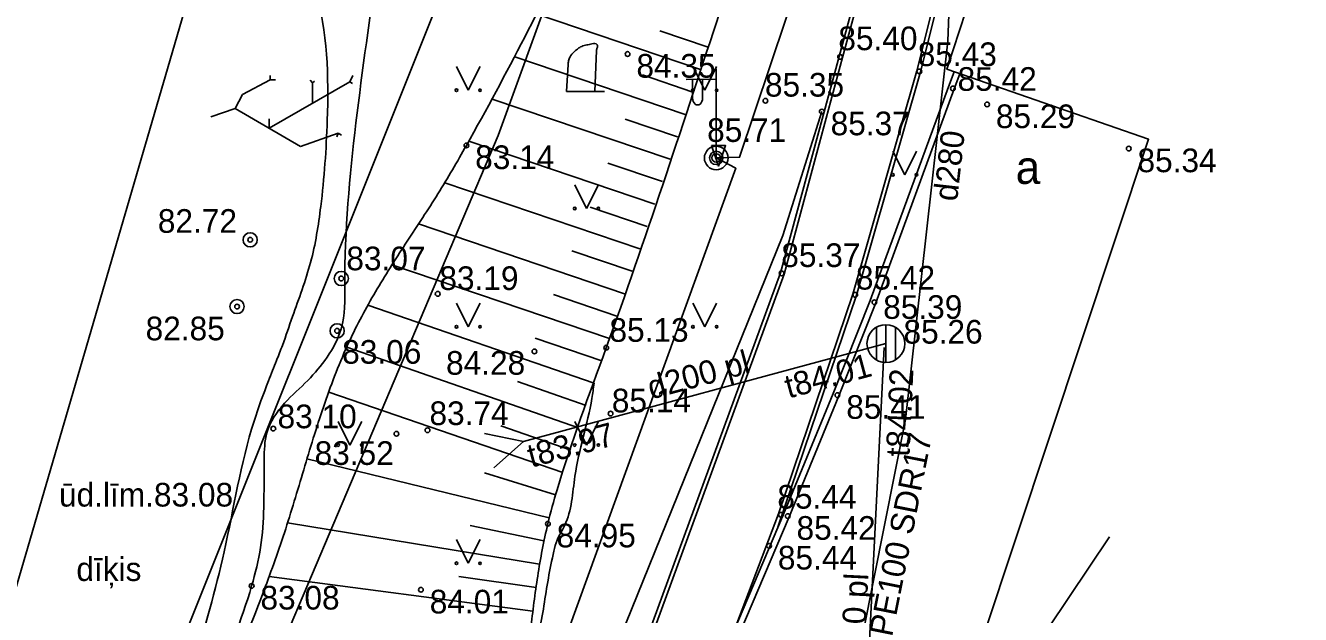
# Model space of a CAD drawing. Extents: x 576692 to 577659, y 273254 to 273799.
# Drawn here: x 576848.14 to 576875.09, y 273561.42 to 273573.87 of the extents above; entities that cross this region are included whole.
import ezdxf

# ---------------------------------------------------------------- set-up
doc = ezdxf.new("R2010")
doc.units = 0
for name, color, linetype in [('BUVE_DUMI_####_####_#', 7, 'Continuous'), ('BUVE_EKAS_####_####_#', 7, 'Continuous'), ('BUVE_EKAS_ADRS_TKST_#', 7, 'Continuous'), ('BUVE_EKAS_VNOS_TKST_#', 7, 'Continuous'), ('CELI_CMAL_####_####_#', 7, 'Continuous'), ('CELI_TAKA_####_####_#', 7, 'Continuous'), ('ELEK_STUT_####_####_#', 7, 'Continuous'), ('ELEK_VADP_ZSPR_####_#', 7, 'Continuous'), ('ELEK_VADV_ZSPR_TKST_#', 7, 'Continuous'), ('GAZE_ELEM_####_####_#', 7, 'Continuous'), ('GAZE_VADP_ZSPD_TKST_#', 7, 'Continuous'), ('GEOD_SITP_####_TKST_#', 7, 'Continuous'), ('HIDT_CAUR_####_TKST_#', 7, 'Continuous'), ('HIDT_REZV_####_TKST_#', 7, 'Continuous'), ('Level 46', 7, 'Continuous'), ('LKAN_ELEM_####_####_#', 7, 'Continuous'), ('LKAN_ELEM_PAST_TKST_#', 7, 'Continuous'), ('LKAN_VADP_PAST_####_I', 7, 'Continuous'), ('NORB_ELEM_####_####_#', 7, 'Continuous'), ('NORB_ZOGS_ZSTP_####_#', 7, 'Continuous'), ('RELJ_ELEM_####_####_#', 7, 'Continuous'), ('SAKK_KKAN_####_####_#', 7, 'Continuous'), ('SAKT_ELEM_####_####_#', 7, 'Continuous'), ('SILT_VADP_UDEN_####_#', 7, 'Continuous'), ('TERT_DIAM_####_TKST_#', 7, 'Continuous'), ('TERT_IZMT_####_TKST_#', 7, 'Continuous'), ('TERT_KONT_####_####_#', 7, 'Continuous'), ('TERT_KRND_####_####_#', 7, 'Continuous'), ('UDTK_VADP_UDEN_####_#', 7, 'Continuous')]:
    doc.layers.add(name, color=color, linetype=linetype)

msp = doc.modelspace()

# ---------------------------------------------------------------- linework, layer by layer
at = {"layer": 'BUVE_EKAS_####_####_#'}
msp.add_line((576867.65, 273572.572), (576867.769, 273572.889), dxfattribs=at)
for points in [[(576872.524, 273601.554), (576871.549, 273595.701), (576870.466, 273589.844), (576869.957, 273588.102), (576868.426, 273583.638), (576867.442, 273580.676), (576866.71, 273578.276), (576865.337, 273573.21), (576864.099, 273568.638), (576860.979, 273560.111), (576855.397, 273548.516), (576851.429, 273541.409), (576846.31, 273533.145), (576841.007, 273525.445), (576837.465, 273520.678), (576833.294, 273515.306), (576829.531, 273511.07)], [(576872.603, 273601.541), (576871.628, 273595.687), (576870.544, 273589.825), (576870.033, 273588.077), (576868.502, 273583.612), (576867.518, 273580.651), (576866.787, 273578.254), (576865.414, 273573.189), (576864.175, 273568.613), (576861.053, 273560.08), (576855.468, 273548.479), (576851.498, 273541.368), (576846.377, 273533.101), (576841.072, 273525.398), (576837.529, 273520.63), (576833.355, 273515.255), (576829.586, 273511.012)], [(576874.399, 273600.589), (576874.091, 273600.456), (576873.946, 273600.177), (576872.621, 273592.28), (576872.31, 273590.551), (576871.737, 273588.382), (576871.426, 273587.391), (576870.11, 273583.537), (576867.982, 273576.895), (576866.982, 273572.91), (576865.628, 273568.191), (576864.056, 273563.546), (576863.156, 273561.168)], [(576874.431, 273600.515), (576874.149, 273600.394), (576874.023, 273600.151), (576872.7, 273592.267), (576872.388, 273590.534), (576871.814, 273588.36), (576871.502, 273587.366), (576870.186, 273583.512), (576868.059, 273576.873), (576867.059, 273572.89), (576865.705, 273568.168), (576864.045, 273563.262)], [(576867.772, 273572.528), (576867.892, 273572.847)], [(576830.649, 273509.884), (576834.382, 273514.243), (576838.438, 273519.296), (576842.214, 273524.414), (576847.656, 273532.314), (576852.745, 273540.529), (576856.712, 273547.652), (576862.459, 273559.523), (576864.161, 273563.536), (576865.211, 273566.091), (576865.992, 273568.054), (576867.65, 273572.572)], [(576830.738, 273509.789), (576834.482, 273514.16), (576838.541, 273519.217), (576842.319, 273524.339), (576847.765, 273532.243), (576852.857, 273540.463), (576856.828, 273547.592), (576862.577, 273559.47), (576864.281, 273563.485), (576865.332, 273566.043), (576866.113, 273568.007), (576867.772, 273572.528)]]:
    msp.add_lwpolyline(points, dxfattribs=at)
at = {"layer": 'BUVE_EKAS_ADRS_TKST_#'}
for p, q in [((576853.313, 273572.721), (576853.313, 273572.812)), ((576855, 273572.675), (576855.058, 273572.811)), ((576852.732, 273572.41), (576853.313, 273572.721)), ((576853.294, 273571.698), (576855, 273572.675)), ((576853.313, 273572.721), (576853.427, 273572.721)), ((576854.206, 273572.655), (576854.161, 273572.71)), ((576854.206, 273572.655), (576854.249, 273572.691)), ((576854.206, 273572.22), (576854.206, 273572.655)), ((576855, 273572.675), (576855.055, 273572.642)), ((576852.576, 273572.117), (576852.732, 273572.41)), ((576852.058, 273571.938), (576852.576, 273572.117)), ((576852.576, 273572.117), (576853.956, 273571.311)), ((576853.294, 273571.698), (576853.294, 273571.898)), ((576853.956, 273571.311), (576854.754, 273571.589)), ((576854.754, 273571.589), (576854.723, 273571.516)), ((576854.754, 273571.589), (576854.822, 273571.549))]:
    msp.add_line(p, q, dxfattribs=at)
for centre in [(576852.891, 273569.338), (576854.817, 273568.52), (576852.613, 273567.927), (576854.729, 273567.414)]:
    msp.add_circle(centre, 0.15, dxfattribs=at)
at = {"layer": 'BUVE_EKAS_VNOS_TKST_#'}
msp.add_lwpolyline([(576863.749, 273554.185), (576865.629, 273559.935), (576866.744, 273565.541), (576867.64, 273573.538), (576867.908, 273580.684)], dxfattribs=at)
at = {"layer": 'CELI_TAKA_####_####_#'}
for points in [[(577046.926, 273445.044), (577014.811, 273425.219), (577003.88, 273430.992), (576984.145, 273436.674), (576957.338, 273444.294), (576939.479, 273446.802), (576902.067, 273445.778), (576895.402, 273442.827), (576880.902, 273442.095), (576847.668, 273445.309), (576837.012, 273452.428), (576828.656, 273463.092), (576806.624, 273484.507), (576830.977, 273509.535), (576825.208, 273515.66), (576822.783, 273520.141), (576835.572, 273532.408), (576845.616, 273554.029), (576851.92, 273575.614), (576848.447, 273595.284), (576850.413, 273611.975)], [(576875.901, 273608.92), (576873.238, 273590.115), (576867.618, 273572.942), (576871.879, 273571.462), (576866.284, 273554.628), (576861.302, 273546.668), (576863.144, 273537.44), (576882.478, 273539.149), (576882.478, 273547.068), (576949.529, 273561.695), (576947.673, 273570.204), (576952.647, 273577.562), (576971.581, 273573.757), (576961.116, 273540.729), (576960.89, 273535.214), (576957.213, 273535.221), (576957.586, 273512.35), (577020.812, 273504.477), (577024.699, 273507.761), (577034.918, 273498.457), (577056.159, 273496.649)]]:
    msp.add_lwpolyline(points, dxfattribs=at)
at = {"layer": 'ELEK_STUT_####_####_#'}
msp.add_spline([(576834.972, 273524.846), (576834.981, 273524.858), (576835.076, 273524.972), (576835.584, 273525.586), (576836.158, 273526.138), (576836.592, 273526.462), (576837.181, 273526.962), (576837.416, 273527.441), (576837.427, 273527.666), (576837.401, 273527.894), (576837.373, 273528.121), (576837.379, 273528.346), (576837.512, 273528.905), (576839.387, 273532.93), (576840.983, 273536.22), (576844.889, 273545.065), (576846.213, 273548.112), (576848.25, 273552.277), (576849.905, 273555.581), (576850.972, 273558.076), (576851.693, 273560.342), (576852.34, 273562.741), (576852.972, 273565.505), (576853.28, 273566.359), (576853.448, 273566.787), (576853.572, 273567.107), (576853.785, 273567.715), (576854.168, 273568.861), (576854.383, 273570.043), (576854.52, 273571.86), (576854.267, 273574.626), (576854.166, 273574.92), (576854.037, 273575.203), (576853.91, 273575.486), (576853.818, 273575.781), (576853.767, 273576.515), (576853.826, 273577.256), (576853.898, 273577.998), (576853.888, 273578.732), (576853.807, 273579.184), (576853.694, 273579.634), (576853.591, 273580.086), (576853.539, 273580.542), (576853.502, 273583.663), (576853.535, 273586.13), (576853.544, 273586.746), (576853.569, 273587.054), (576853.626, 273587.362), (576854.091, 273587.713), (576855.035, 273587.927), (576855.509, 273587.995), (576856.157, 273588.043), (576856.618, 273588.065), (576856.725, 273588.125), (576856.752, 273588.242), (576856.674, 273588.341), (576856.515, 273588.366), (576855.448, 273588.455), (576855.093, 273588.426), (576854.738, 273588.366), (576854.383, 273588.3), (576854.028, 273588.254), (576853.388, 273588.304), (576853.149, 273588.568), (576853.124, 273588.995), (576853.2, 273591.212), (576853.212, 273592.376), (576853.166, 273592.947), (576853.072, 273593.225), (576852.923, 273593.494), (576852.604, 273593.842), (576852.245, 273594.123), (576851.604, 273594.55), (576851.252, 273595.166), (576851.252, 273596.146), (576851.403, 273598.132), (576851.927, 273600.965), (576852.459, 273603.438)], degree=3, dxfattribs=at)
at = {"layer": 'ELEK_VADP_ZSPR_####_#'}
msp.add_lwpolyline([(576858.668, 273565.077), (576866.328, 273567.144)], dxfattribs=at)
at = {"layer": 'ELEK_VADV_ZSPR_TKST_#'}
for points in [[(576865.709, 273555.378), (576866.292, 273567.062)], [(576865.867, 273555.326), (576871.052, 273563.06)]]:
    msp.add_lwpolyline(points, dxfattribs=at)
at = {"layer": 'GAZE_ELEM_####_####_#'}
for p, q in [((576862.407, 273572.935), (576858.934, 273574.114)), ((576862.568, 273573.409), (576861.548, 273573.755)), ((576862.086, 273571.988), (576858.463, 273573.216)), ((576862.247, 273572.462), (576861.182, 273572.822)), ((576861.765, 273571.041), (576857.988, 273572.319)), ((576861.926, 273571.515), (576860.816, 273571.891)), ((576861.445, 273570.094), (576857.511, 273571.425)), ((576861.605, 273570.567), (576860.449, 273570.959)), ((576861.124, 273569.147), (576857.002, 273570.542)), ((576861.285, 273569.62), (576860.079, 273570.028)), ((576860.804, 273568.199), (576856.448, 273569.674)), ((576860.964, 273568.673), (576859.693, 273569.103)), ((576860.483, 273567.252), (576855.888, 273568.808)), ((576860.159, 273566.306), (576855.379, 273567.958)), ((576860.643, 273567.726), (576859.3, 273568.181)), ((576860.322, 273566.779), (576858.914, 273567.261)), ((576859.83, 273565.362), (576854.931, 273567.07)), ((576859.995, 273565.834), (576858.541, 273566.341)), ((576859.502, 273564.417), (576854.55, 273566.116)), ((576859.666, 273564.89), (576858.187, 273565.405)), ((576859.213, 273563.461), (576854.091, 273564.707)), ((576859.342, 273563.944), (576857.842, 273564.413)), ((576859.009, 273562.482), (576853.682, 273563.358)), ((576859.101, 273562.973), (576857.541, 273563.302)), ((576858.866, 273561.492), (576853.295, 273562.222)), ((576858.933, 273561.988), (576857.3, 273562.22))]:
    msp.add_line(p, q, dxfattribs=at)
msp.add_spline([(576837.927, 273521.787), (576838.645, 273522.875), (576839.138, 273523.968), (576839.325, 273524.31), (576840.566, 273526.148), (576844.476, 273531.952), (576846.478, 273535.631), (576849.875, 273542.091), (576852.37, 273547.073), (576852.835, 273547.871), (576853.349, 273548.641), (576853.868, 273549.409), (576854.351, 273550.199), (576857.795, 273557.24), (576858.42, 273558.892), (576858.657, 273559.995), (576858.817, 273561.113), (576858.969, 273562.231), (576859.183, 273563.337), (576859.378, 273564.056), (576860.417, 273567.058), (576862.753, 273573.954), (576864.533, 273579.174), (576866.114, 273583.695), (576866.428, 273584.761), (576866.683, 273585.844), (576866.928, 273586.93), (576867.213, 273588.005), (576867.419, 273588.612), (576867.767, 273589.444), (576868.162, 273590.255), (576868.541, 273591.08), (576868.705, 273591.507), (576868.841, 273591.951), (576868.878, 273592.605), (576868.852, 273593.138), (576868.802, 273593.672), (576868.76, 273594.206), (576868.758, 273594.74), (576868.878, 273595.276), (576870.132, 273598.247), (576870.705, 273599.436), (576871.14, 273600.337), (576871.192, 273600.445), (576871.479, 273601.144)], degree=3, dxfattribs=at)
at = {"layer": 'GEOD_SITP_####_TKST_#'}
msp.add_spline([(576860.159, 273566.306), (576860.113, 273565.987), (576859.755, 273564.34), (576859.537, 273563.302), (576859.377, 273562.992), (576859.31, 273562.756), (576859.193, 273562.183), (576859.099, 273561.604), (576858.839, 273560.463), (576858.659, 273560.007)], degree=3, dxfattribs=at)
at = {"layer": 'Level 46'}
msp.add_lwpolyline([(576819.084, 273508.06), (576836.748, 273524.115), (576867.586, 273601.172), (576868.039, 273663.467), (576868.105, 273672.497), (576868.105, 273672.497)], dxfattribs=at)
at = {"layer": 'LKAN_ELEM_####_####_#'}
msp.add_lwpolyline([(576849.004, 273551.431), (576853.733, 273561.172), (576858.13, 273571.54), (576862.062, 273582.382), (576864.74, 273591.4), (576865.79, 273595.589), (576867.357, 273605.525), (576868.834, 273616.371), (576869.677, 273625.341)], dxfattribs=at)
at = {"layer": 'LKAN_ELEM_PAST_TKST_#'}
for p, q in [((576860.179, 273572.473), (576860.213, 273573.338)), ((576857.25, 273573), (576857.5, 273572.5)), ((576857.5, 273572.5), (576857.75, 273573)), ((576859.61, 273573.046), (576859.579, 273572.473)), ((576862.25, 273573), (576862.5, 273572.5)), ((576862.5, 273572.5), (576862.75, 273573)), ((576860.179, 273572.473), (576859.579, 273572.473)), ((576859.579, 273572.473), (576859.879, 273572.473)), ((576859.879, 273572.473), (576860.179, 273572.473)), ((576860.179, 273572.473), (576860.379, 273572.473)), ((576866.475, 273571.213), (576866.725, 273570.713)), ((576866.725, 273570.713), (576866.975, 273571.213)), ((576859.75, 273570.5), (576860, 273570)), ((576860, 273570), (576860.25, 273570.5)), ((576857.25, 273568), (576857.5, 273567.5)), ((576857.5, 273567.5), (576857.75, 273568)), ((576862.25, 273568), (576862.5, 273567.5)), ((576862.5, 273567.5), (576862.75, 273568)), ((576854.75, 273565.5), (576855, 273565)), ((576855, 273565), (576855.25, 273565.5)), ((576859.75, 273565.5), (576860, 273565)), ((576860, 273565), (576860.25, 273565.5)), ((576857.25, 273563), (576857.5, 273562.5)), ((576857.5, 273562.5), (576857.75, 273563))]:
    msp.add_line(p, q, dxfattribs=at)
for centre, radius in [((576857.25, 273572.5), 0.028), ((576857.75, 273572.5), 0.0263), ((576862.25, 273572.5), 0.028), ((576862.75, 273572.5), 0.0263), ((576866.475, 273570.713), 0.028), ((576866.975, 273570.713), 0.0263), ((576859.75, 273570), 0.028), ((576860.25, 273570), 0.0263), ((576857.25, 273567.5), 0.028), ((576857.75, 273567.5), 0.0263), ((576862.25, 273567.5), 0.028), ((576862.75, 273567.5), 0.0263), ((576854.75, 273565), 0.028), ((576855.25, 273565), 0.0263), ((576859.75, 273565), 0.028), ((576860.25, 273565), 0.0263), ((576857.25, 273562.5), 0.028), ((576857.75, 273562.5), 0.0263)]:
    msp.add_circle(centre, radius, dxfattribs=at)
msp.add_spline([(576860.213, 273573.338), (576860.217, 273573.369), (576860.22, 273573.38), (576860.235, 273573.442), (576860.205, 273573.477), (576860.083, 273573.471), (576859.979, 273573.453), (576859.873, 273573.414), (576859.808, 273573.37), (576859.733, 273573.306), (576859.653, 273573.208), (576859.622, 273573.119), (576859.61, 273573.045)], degree=3, dxfattribs=at)
at = {"layer": 'LKAN_VADP_PAST_####_I'}
msp.add_spline([(576835.08, 273524.732), (576835.565, 273525.331), (576835.899, 273525.691), (576836.182, 273525.922), (576836.697, 273526.287), (576837.155, 273526.713), (576837.431, 273527.117), (576837.552, 273527.533), (576837.586, 273527.882), (576837.546, 273528.26), (576837.58, 273528.832), (576837.914, 273529.4), (576838.818, 273530.936), (576840.37, 273534.29), (576841.226, 273536.313), (576843.234, 273540.596), (576845.228, 273545.145), (576847.347, 273549.287), (576848.441, 273551.415), (576849.511, 273553.764), (576850.461, 273555.635), (576851.331, 273557.747), (576852.143, 273559.881), (576852.922, 273562.023), (576853.11, 273562.836), (576853.177, 273563.681), (576853.187, 273564.699), (576853.244, 273565.26), (576853.618, 273565.884), (576854.109, 273566.366), (576854.516, 273566.855), (576854.814, 273567.456), (576854.89, 273568.375), (576855.567, 273575.201), (576855.677, 273576.074), (576855.787, 273576.781), (576855.86, 273577.3), (576855.946, 273578.276), (576855.805, 273578.856), (576855.449, 273579.483), (576855.049, 273580.113), (576854.793, 273580.901), (576854.708, 273581.412), (576854.663, 273581.99), (576854.655, 273582.742), (576854.539, 273583.533), (576854.19, 273584.72), (576853.901, 273586.393), (576853.792, 273586.803), (576853.701, 273587.162), (576853.716, 273587.278), (576853.754, 273587.393), (576853.994, 273587.609), (576854.323, 273587.707), (576855.548, 273587.944), (576856.825, 273588.054), (576856.837, 273588.398), (576856.091, 273588.478), (576855.172, 273588.484), (576854.605, 273588.397), (576853.846, 273588.306), (576853.427, 273588.398), (576853.385, 273588.603), (576853.429, 273589.465), (576853.518, 273590.327), (576853.604, 273591.189), (576853.568, 273592.189), (576853.297, 273593.595), (576853.086, 273593.989), (576852.576, 273594.449), (576852.159, 273594.771), (576851.894, 273595.184), (576851.785, 273596.323), (576851.789, 273597.359), (576851.805, 273598.234), (576851.957, 273600.453), (576853.017, 273604.414), (576853.411, 273606.075), (576853.854, 273607.267), (576854.162, 273607.705), (576854.645, 273608.227), (576855.009, 273608.628), (576855.411, 273609.701), (576855.403, 273610.6), (576855.092, 273611.095), (576854.646, 273611.543), (576854.18, 273611.989), (576853.805, 273612.473), (576853.513, 273613.117), (576853.268, 273613.805), (576852.993, 273614.48), (576852.61, 273615.087), (576852.115, 273615.793), (576851.84, 273615.988), (576851.648, 273616.135), (576851.565, 273616.382), (576851.61, 273616.975)], degree=3, dxfattribs=at)
at = {"layer": 'NORB_ELEM_####_####_#'}
msp.add_lwpolyline([(576864.974, 273572.048), (576864.149, 273569.428), (576857.509, 273553.03), (576855.723, 273549.389), (576853.819, 273545.947), (576851.872, 273542.38), (576849.207, 273538.273), (576845.539, 273532.263), (576841.007, 273525.62), (576838.644, 273522.452), (576836.243, 273519.237), (576831.205, 273513.094), (576829.454, 273511.151)], dxfattribs=at)
at = {"layer": 'RELJ_ELEM_####_####_#'}
msp.add_lwpolyline([(576862.64, 273571.331), (576862.94, 273571.331), (576862.79, 273570.898)], close=True, dxfattribs=at)
for centre in [(576860.869, 273573.265), (576865.361, 273573.203), (576867.035, 273572.896), (576867.744, 273572.538), (576863.782, 273572.278), (576864.974, 273572.048), (576868.467, 273572.199), (576857.461, 273571.333), (576871.46, 273571.267), (576852.891, 273569.338), (576854.817, 273568.52), (576864.123, 273568.63), (576856.854, 273568.196), (576865.681, 273568.175), (576852.613, 273567.927), (576866.085, 273568.018), (576854.729, 273567.414), (576858.898, 273566.979), (576860.417, 273567.058), (576865.304, 273566.054), (576860.509, 273565.664), (576853.38, 273565.347), (576855.983, 273565.238), (576856.639, 273565.314), (576859.183, 273563.337), (576864.108, 273563.527), (576864.253, 273563.497), (576863.859, 273562.869), (576852.922, 273562.023), (576856.5, 273561.94)]:
    msp.add_circle(centre, 0.05, dxfattribs=at)
at = {"layer": 'SAKT_ELEM_####_####_#'}
msp.add_spline([(576868.325, 273601.659), (576868.279, 273601.285), (576868.019, 273600.533), (576867.639, 273599.832), (576867.238, 273599.142), (576866.911, 273598.42), (576866.342, 273596.673), (576865.892, 273594.891), (576865.805, 273594.295), (576865.752, 273593.694), (576865.699, 273593.093), (576865.611, 273592.498), (576864.613, 273588.736), (576864.28, 273587.867), (576863.909, 273587.014), (576863.538, 273586.162), (576863.201, 273585.299), (576862.788, 273583.909), (576862.449, 273582.492), (576862.092, 273581.081), (576861.626, 273579.706), (576859.874, 273575.941), (576857.461, 273571.333), (576856.858, 273570.309), (576856.211, 273569.31), (576855.577, 273568.303), (576855.016, 273567.255), (576854.497, 273565.968), (576854.072, 273564.644), (576853.668, 273563.312), (576853.21, 273562.001), (576852.348, 273559.815), (576851.475, 273557.633), (576849.613, 273553.315), (576848.546, 273551.137), (576847.423, 273548.988), (576846.299, 273546.839), (576845.231, 273544.663), (576841.367, 273535.944), (576839.109, 273530.254), (576838.394, 273528.504), (576838.008, 273527.64), (576837.587, 273526.79), (576837.19, 273526.291), (576836.672, 273525.894), (576836.125, 273525.518), (576835.646, 273525.083), (576835.223, 273524.56)], degree=3, dxfattribs=at)
at = {"layer": 'SILT_VADP_UDEN_####_#'}
msp.add_lwpolyline([(576868.105, 273672.497), (576868.039, 273663.467), (576867.586, 273601.172), (576836.748, 273524.115), (576819.084, 273508.06)], dxfattribs=at)
at = {"layer": 'TERT_DIAM_####_TKST_#'}
for p, q in [((576862.742, 273571.068), (576862.742, 273572.951)), ((576862.742, 273572.735), (576862.107, 273572.73)), ((576862.242, 273572.731), (576862.242, 273572.339)), ((576862.452, 273572.733), (576862.452, 273572.339))]:
    msp.add_line(p, q, dxfattribs=at)
for radius in [0.25, 0.09]:
    msp.add_circle((576862.742, 273571.068), radius, dxfattribs=at)
msp.add_ellipse((576862.347, 273572.339), major_axis=(0, 0.151), ratio=0.695971, start_param=1.570796, end_param=4.712389, dxfattribs=at)
at = {"layer": 'TERT_KONT_####_####_#'}
for radius in [0.141, 0.0126]:
    msp.add_circle((576862.742, 273571.068), radius, dxfattribs=at)
at = {"layer": 'TERT_KRND_####_####_#'}
msp.add_lwpolyline([(576872.377, 273604.118), (576872.209, 273602.191), (576871.992, 273600.21), (576869.75, 273590.5), (576863.235, 273571.084), (576862.742, 273571.068), (576863.155, 273570.852), (576859.6, 273561.036)], dxfattribs=at)
at = {"layer": 'UDTK_VADP_UDEN_####_#'}
for p, q in [((576866.128, 273566.798), (576866.128, 273567.49)), ((576866.328, 273566.744), (576866.328, 273567.544)), ((576866.528, 273566.798), (576866.528, 273567.49)), ((576858.668, 273565.077), (576857.846, 273565.242)), ((576858.043, 273564.518), (576858.668, 273565.077))]:
    msp.add_line(p, q, dxfattribs=at)
msp.add_circle((576866.328, 273567.144), 0.4, dxfattribs=at)

# ---------------------------------------------------------------- texts
at = {"layer": 'BUVE_DUMI_####_####_#'}
for s, rotation, p in [('d280', 83.605, (576867.832, 273570.139)), ('PE100 SDR17', 78.7525, (576866.457, 273560.931))]:
    msp.add_text(s, height=0.5, rotation=rotation, dxfattribs=at).set_placement(p)
at = {"layer": 'CELI_CMAL_####_####_#'}
msp.add_text('a', height=0.7, dxfattribs=at).set_placement((576869.07, 273570.52))
at = {"layer": 'GAZE_VADP_ZSPD_TKST_#'}
for s, p in [('ūd.līm.83.08', (576848.85, 273563.7)), ('dīķis', (576849.217, 273562.127))]:
    msp.add_text(s, height=0.5, dxfattribs=at).set_placement(p)
at = {"layer": 'HIDT_CAUR_####_TKST_#'}
msp.add_text('t84.02', height=0.5, rotation=87.3652, dxfattribs=at).set_placement((576866.825, 273564.745))
at = {"layer": 'HIDT_REZV_####_TKST_#'}
for s, p in [(' 85.40', (576865.137, 273573.346)), (' 85.43', (576866.814, 273573.01)), (' 84.35', (576860.869, 273572.765)), (' 85.35', (576863.586, 273572.365)), (' 85.42', (576867.658, 273572.487)), (' 85.37', (576864.974, 273571.548)), (' 85.29', (576868.467, 273571.699)), (' 85.71', (576862.363, 273571.407)), (' 83.14', (576857.461, 273570.833)), (' 85.34', (576871.46, 273570.767)), (' 85.37', (576863.931, 273568.763)), (' 83.19', (576856.704, 273568.277)), (' 85.42', (576865.508, 273568.286)), (' 85.39', (576866.085, 273567.667)), (' 85.13', (576860.299, 273567.182)), (' 84.28', (576856.845, 273566.486)), (' 85.14', (576860.349, 273565.69)), (' 85.41', (576865.304, 273565.554)), (' 83.10', (576853.284, 273565.355)), (' 83.74', (576856.495, 273565.422)), (' 83.52', (576854.067, 273564.58)), (' 85.44', (576863.848, 273563.655)), (' 85.42', (576864.253, 273562.997)), (' 84.95', (576859.183, 273562.837)), (' 85.44', (576863.859, 273562.369)), (' 83.08', (576852.922, 273561.523)), (' 84.01', (576856.5, 273561.44))]:
    msp.add_text(s, height=0.5, dxfattribs=at).set_placement(p)
at = {"layer": 'NORB_ZOGS_ZSTP_####_#'}
for s, p in [(' 82.72', (576850.753, 273569.486)), (' 83.07', (576854.738, 273568.694)), (' 82.85', (576850.495, 273567.214)), (' 83.06', (576854.65, 273566.719))]:
    msp.add_text(s, height=0.5, dxfattribs=at).set_placement(p)
at = {"layer": 'SAKK_KKAN_####_####_#'}
msp.add_text('  85.26', height=0.5, dxfattribs=at).set_placement((576866.328, 273567.144))
at = {"layer": 'TERT_IZMT_####_TKST_#'}
for s, rotation, p in [('d200 pl', 15.1012, (576861.369, 273565.961)), ('t84.01', 15.1012, (576864.271, 273565.981)), ('t83.97', 15.1012, (576858.832, 273564.519)), ('d200 pl', 87.145, (576865.849, 273560.088))]:
    msp.add_text(s, height=0.5, rotation=rotation, dxfattribs=at).set_placement(p)

doc.saveas('drawing.dxf')
